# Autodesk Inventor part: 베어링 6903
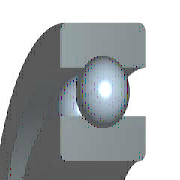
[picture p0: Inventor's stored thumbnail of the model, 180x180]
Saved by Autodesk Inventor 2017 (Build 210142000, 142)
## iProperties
Created: 2012-02
Part Number: 베어링 6903
Material: 강철, 연강
Description: 깊은 그루브 볼 베어링
Document SubType Name: Modeling
Standard: KS B 2023
Designer: mduedu
Standards Organization: KS
Language: ko-KR
Size Designation: 6003 - 17 x 35 x 10
Categories: <MemberInstance><Categories><Category DisplayName="샤프트 부품" InternalName="7f7aeb1f-a693-4053-b835-cee3144e0d98" Mnemonic="SHFT"><Category DisplayName="베어링" Inter
Density: 1 g/cm^3
Appearance: 터키옥색
IsCustomPart: 1
Author: mduedu
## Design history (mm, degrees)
sketch "스케치" dims "d0" = 3.38 (= -0.26 x WD + 0.26 x BD)
  geometry: L1 (1.81, 11.75)-(5.19, 11.75); L2 (3.5, 11.75)-(3.5, 10.06); L3 (3.5, 11.75)-(3.5, 13.44); L4 (2.244, 10.619)-(0, 10.619); L5 (0, 8.5)-(7, 8.5); L6 (2.244, 12.881)-(0, 12.881); L7 (0, 15)-(7, 15); L8 (7, 8.5)-(7, 10.619); L9 (4.756, 10.619)-(7, 10.619); L10 (4.756, 12.881)-(7, 12.881); L11 (7, 15)-(7, 12.881); L12 (-2, 0)-(12, 0) reference; L13 (0, 7.2)-(0, 16.3) reference; 1 other entity
  constraints: 22 end point, 4 point on line, 2 collinear, 2 perpendicular, 2 symmetric about line, 1 midpoint, 1 parallel, 14 other
  dimensions: "d9" = 17 diameter of L5 L12 (= WD); "d11" = 30 diameter of L7 L12 (= BD); "d12" = 7 distance between parallel lines of L8 L13 (= KB); "d13" = 21.238 diameter of L9 L12 (= 0.326 x BD + 0.674 x WD)
revolve "본체" stored, may be unused: angle "d6" = 90 deg
revolve "볼" stored, may be unused: angle "d7" = 90 deg
pattern_circular "IDS_ARRAYBALL[SIMPL:T]" dims angle "d3" = 360 deg
body "Solid1"
fillet "모깎기1" dims "d1" = 0.3 (= KRS)
other parameters: "WD" = 17 [user parameter; used in 5 equation terms], "BD" = 30 [user parameter; used in 5 equation terms], "KB" = 7 [user parameter; used in 1 equation term], "KRS" = 0.3 [user parameter; used in 1 equation term], "d4" = 0, "d5" = 0, "d8" = 0, "d14" = 0, "d15" = 0, "BBA" = 0 [user parameter], "BC0" = 3250000 [user parameter], "BC" = 6050000 [user parameter], "BR" = 15 (= 0.5 x BD) [user parameter], "WR" = 8.5 (= 0.5 x WD) [user parameter]
